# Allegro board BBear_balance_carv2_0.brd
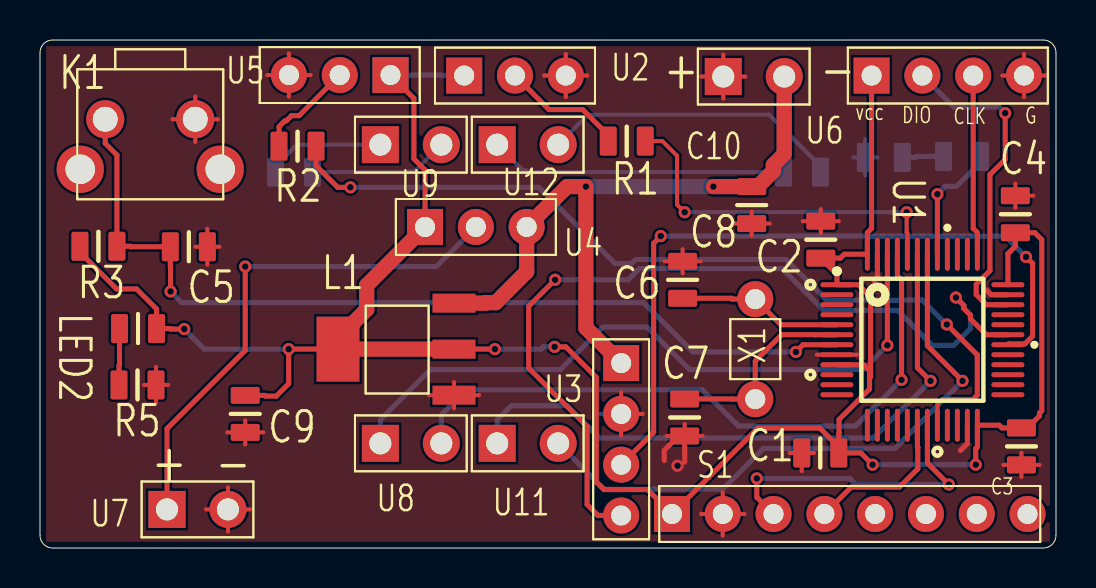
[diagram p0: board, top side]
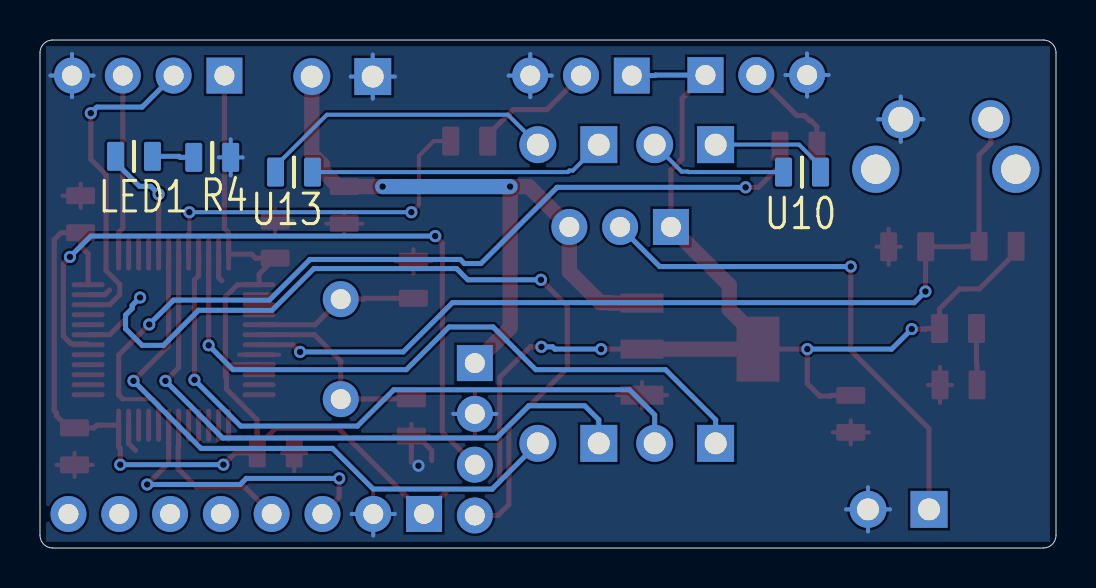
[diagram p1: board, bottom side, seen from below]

Outline 50.8 x 25.4 mm; copper layers: TOP, BOTTOM. Coordinates in mm from the lower left corner of the outline.
Outline path: 0,24.77 arc(0.19,25.21) 0.63,25.4 50.16,25.4 arc(50.61,25.21) 50.8,24.77 50.8,0.63 arc(50.61,0.19) 50.16,0 0.63,0 arc(0.19,0.19) 0,0.63 0,24.77

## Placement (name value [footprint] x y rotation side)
C1  0.1UF  [C-0805]  39.01 4.75 0 top
C2  0.1UF  [C-0805]  39.04 15.42 270 top
C3  0.1UF  [C-0805]  49.07 5.08 90 top
C4  0.1UF  [C-0805]  48.77 16.69 270 top
C5  1UF  [C-0805]  7.44 15.06 180 top
C6  22PF  [C-0805]  32.13 13.41 270 top
C7  22PF  [C-0805]  32.23 6.53 90 top
C8  0.1UF  [C-0805]  35.59 17.14 270 top
C9  10UF  [C-0805]  10.26 6.71 90 top
C10  POWER  [CON2_R2_54]  34.16 23.57 90 top
K1  KEY-4  [BUTTON_6X6X5]  5.51 21.44 180 top
L1  LM1117  [LM1117_3_3]  20.7 12.24 180 top
LED1  HEARTLED  [C-0805]  46.1 19.58 0 bottom
LED2  POWER  [C-0805]  4.9 10.97 0 top
R1  10K  [C-0805]  29.34 20.35 0 top
R2  10K  [C-0805]  12.88 20.09 0 top
R3  10K  [C-0805]  2.92 15.09 0 top
R4  1K  [C-0805]  42.19 19.53 180 bottom
R5  1K  [C-0805]  4.88 8.15 0 top
S1  MPU6050  [CON8]  31.6 1.7 90 top
U1  STM32F103C8T6  [NCU100_LQFP_48]  44.12 10.41 0 top
U2  BOOT0  [CON3]  21.21 23.62 90 top
U3  -  [CON4]  29.06 9.25 0 top
U4  switch  [CON3]  19.25 16.05 90 top
U5  BOOT1  [CON3]  17.53 23.65 270 top
U6  SWD  [CON4]  41.58 23.62 90 top
U7  CON2  [CON2_R2_54]  6.35 1.93 90 top
U8  CON2  [CON2_R2_54]  17.02 5.23 90 top
U9  MOTOR-A  [CON2_R2_54]  17.02 20.17 90 top
U10  MOTOR0805  [C-0805]  12.7 18.8 180 bottom
U11  CON2  [CON2_R2_54]  22.86 5.23 90 top
U12  MOTOR-B  [CON2_R2_54]  22.86 20.17 90 top
U13  MOTOR0805  [C-0805]  38.1 18.8 180 bottom
X1  -  [XTAL]  35.76 7.44 90 top

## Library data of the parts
C1-C9 = CAP: Tolerance: RichardLC; User Part Number: pn
C10 U7-U9 U11 U12 = CON2
K1 = KEY-4
L1 = LM1117
LED1 LED2 = LED: Tolerance: RichardLC; User Part Number: pn
R1-R5 = R: Tolerance: RichardLC; User Part Number: pn
S1 = CON8
U1 = STM32F103C8T6: User Part Number: pn; Tolerance: RichardLC
U2 U4 U5 = CON3
U3 U6 = CON4
U10 U13 = CON2: Tolerance: RichardLC; User Part Number: pn
X1 = XTAL

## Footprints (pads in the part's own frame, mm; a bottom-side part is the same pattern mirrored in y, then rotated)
BUTTON_6X6X5
  round 1.905 hole 1.245: 1(-2.25,0) 2(2.25,0)
  round 2.362 hole 1.473: 3(-3.5,2.5) 4(3.5,2.5)
C-0805
  custom 0.212x0.212 smd: 1(-0.925,0) 2(0.925,0)
CON2_R2_54
  rect 1.849x1.849 hole 1.1: 1(0,0)
  round 1.849 hole 1.1: 2(0,-3.048)
CON3
  rect 1.8x1.8 hole 1: 1(0,0)
  round 1.8 hole 1: 2(0,-2.54) 3(0,-5.08)
CON4
  rect 1.8x1.8 hole 1: 1(0,0)
  round 1.8 hole 1: 2(0,-2.54) 3(0,-5.08) 4(0,-7.62)
CON8
  rect 1.8x1.8 hole 1: 1(0,0)
  round 1.8 hole 1: 2(0,-2.54) 3(0,-5.08) 4(0,-7.62) 5(0,-10.16) 6(0,-12.7) 7(0,-15.24) 8(0,-17.78)
LM1117_3_3
  rect 2.15x0.95 smd: 1(0,0) 2(0,2.3) 3(0,4.6)
  rect 2.15x3.25 smd: 4(5.8,2.3)
NCU100_LQFP_48
  oval 1.651x0.249 smd: 1(-4.275,2.75) 2(-4.275,2.25) 3(-4.275,1.75) 4(-4.275,1.25) 5(-4.275,0.75) 6(-4.275,0.25) 7(-4.275,-0.25) 8(-4.275,-0.75) 9(-4.275,-1.25) 10(-4.275,-1.75) 11(-4.275,-2.25) 12(-4.275,-2.75) 25(4.275,-2.75) 26(4.275,-2.25) 27(4.275,-1.75) 28(4.275,-1.25) 29(4.275,-0.75) 30(4.275,-0.25) 31(4.275,0.25) 32(4.275,0.75) 33(4.275,1.25) 34(4.275,1.75) 35(4.275,2.25) 36(4.275,2.75)
  oval 0.249x1.651 smd: 13(-2.75,-4.275) 14(-2.25,-4.275) 15(-1.75,-4.275) 16(-1.25,-4.275) 17(-0.75,-4.275) 18(-0.25,-4.275) 19(0.25,-4.275) 20(0.75,-4.275) 21(1.25,-4.275) 22(1.75,-4.275) 23(2.25,-4.275) 24(2.75,-4.275) 37(2.75,4.275) 38(2.25,4.275) 39(1.75,4.275) 40(1.25,4.275) 41(0.75,4.275) 42(0.25,4.275) 43(-0.25,4.275) 44(-0.75,4.275) 45(-1.25,4.275) 46(-1.75,4.275) 47(-2.25,4.275) 48(-2.75,4.275)
XTAL
  round 1.8 hole 1: 1(0,0) 2(5,0)

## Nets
GND: C1.1 C2.1 C3.1 C4.1 C5.1 C6.1 C7.1 C8.2 C9.1 C10.1(-) K1.1 L1.3(GND) R4.2 R5.2 S1.2 U1.8(VSSA) U1.23(VSS_1) U1.35(VSS_2) U1.47(VSS_3) U2.3 U3.2 U5.3 U6.4 U7.2
VCC3.3: C1.2 C2.2 C3.2 C4.2 C9.2 L1.2(OUT2) L1.4(OUT1) LED2.2 R3.1 S1.1 U1.1(VBAT) U1.9(VDDA) U1.24(VDD_1) U1.36(VDD_2) U1.48(VDD_3) U2.1 U4.1 U5.1 U6.1
BAT_D: C8.1 C10.2(+) L1.1(VCC-IN) U3.1 U4.3
BOOT0: R1.2 U1.44(BOOT0)
BOOT1: R2.2 U1.20(PB2/BOOT1)
HEART_LED: LED1.2 U1.41(PB5)
LEFT_BACK: U1.43(PB7) U11.1
LEFT_FOR: U1.42(PB6) U11.2
MOTOR_BAT: U4.2 U7.1
OSCIN: C6.2 U1.5(OSCIN) X1.2
OSCOUT: C7.2 U1.6(OSCOUT) X1.1
PA9: U1.31(PA10) U3.4
PA10: U1.30(PA9) U3.3
RESET: C5.2 K1.2 R3.2 U1.7(NRST)
RIGHT_BACK: U1.46(PB9) U8.1
RIGHT_FOR: U1.45(PB8) U8.2
SCL: S1.3 U1.19(PB1)
SDA: S1.4 U1.18(PB0)
SWCLK: U1.37(SWCLK) U6.3
SWIO: U1.34(SWIO) U6.2
N03806: LED2.1 R5.1
N07785: LED1.1 R4.1
N23990: U9.1 U10.2
N23994: U9.2 U10.1
N23998: U12.1 U13.2
N24002: U12.2 U13.1
N073361: R1.1 U2.2
N073541: R2.1 U5.2

Pads without a net: K1 3 4; S1 5 6 7 8; U1 2 3 4 10 11 12 13 14 15 16 17 21 22 25 26 27 28 29 32 33 38 39 40

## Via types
v1: diameter 0.61, hole 0.33, TOP to BOTTOM, 28 vias

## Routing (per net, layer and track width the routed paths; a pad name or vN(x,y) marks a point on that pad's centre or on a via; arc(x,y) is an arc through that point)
GND: length 108.9
  TOP w0.203: U3.2 29.06,7.78 ; U3.2 30.14,6.71 ; U3.2 29.06,5.63 ; 38.84,9.66 U1.8 40.85,9.66 ; 5.8,7.25 R5.2 ; R5.2 5.8,9.06 ; R5.2 6.4,8.15 ; R5.2 5.2,8.15 ; K1.1 8.89,21.44 ; K1.1 6.63,21.44 ; K1.1 7.76,20.31 ; K1.1 7.76,22.57 ; C1.1 38.69,4.75 ; C1.1 37.49,4.75 ; C1.1 38.09,3.85 ; 33.06,23.57 C10.1 ; C10.1 34.16,24.67 ; C10.1 34.16,22.47 ; C10.1 35.27,23.57 ; C2.1 39.94,16.34 ; C2.1 38.14,16.34 ; C2.1 39.04,15.74 ; C2.1 39.04,16.95 ; C8.2 35.59,16.82 ; C8.2 34.68,16.22 ; C8.2 35.59,15.62 ; C8.2 36.49,16.22 ; C4.1 48.77,18.22 ; C4.1 49.67,17.61 ; C4.1 48.77,17.01 ; 26.29,22.54 26.29,23.62 ; 26.29,23.62 25.21,23.62 ; 26.29,23.62 26.29,24.7 ; 26.29,23.62 27.37,23.62 ; 19.45,7.64 L1.3 ; L1.3 20.7,6.99 ; L1.3 20.7,8.3 ; L1.3 21.95,7.64 ; 33.13,5.6 C7.1 32.23,6.21 ; 8.37,14.16 C5.1 ; C5.1 7.76,15.06 ; C5.1 8.97,15.06 ; C5.1 8.37,15.96 ; 48.12,23.62 U6.4 ; U6.4 50.28,23.62 ; U6.4 49.2,24.7 ; U6.4 49.2,22.54 ; 48.17,4.15 C3.1 ; C3.1 49.07,4.76 ; C3.1 49.07,3.55 ; C3.1 49.98,4.15 ; 33.06,1.7 S1.2 ; S1.2 34.14,2.78 ; S1.2 34.14,0.62 ; S1.2 35.22,1.7 ; 12.45,22.57 U5.3 ; U5.3 12.45,24.73 ; U5.3 13.52,23.65 ; U5.3 11.37,23.65 ; 32.13,13.73 C6.1 ; C6.1 33.03,14.34 ; C6.1 31.23,14.34 ; C6.1 32.13,14.94 ; 8.3,1.93 U7.2 ; U7.2 10.5,1.93 ; U7.2 9.4,0.83 ; U7.2 9.4,3.03 ; 31.33,5.6 31.93,5.6 ; 10.26,5.18 C9.1 ; C9.1 11.16,5.78 ; C9.1 9.36,5.78 ; C9.1 10.26,6.38
  TOP w0.254: U1.47 41.87,13.52 41.71,13.36 ; U1.23 46.37,5.22 46.02,4.88 ; U1.35 47.56,12.66 47.32,12.9 ; 31.22,4.37 31.22,4.89 31.93,5.6 C7.1 32.23,4.29
  BOTTOM w0.203: U7.2 10.5,1.93 ; U7.2 9.4,3.03 ; U7.2 8.3,1.93 ; U7.2 9.4,0.83 ; 33.06,1.7 S1.2 ; S1.2 35.22,1.7 ; S1.2 34.14,0.62 ; U6.4 50.28,23.62 ; U6.4 49.2,22.54 ; U6.4 48.12,23.62 ; U6.4 49.2,24.7 ; 7.76,20.31 K1.1 ; K1.1 7.76,22.57 ; K1.1 8.89,21.44 ; K1.1 6.63,21.44 ; 26.29,23.62 26.29,24.7 ; 26.29,23.62 26.29,22.54 ; 26.29,23.62 25.21,23.62 ; 26.29,23.62 27.37,23.62 ; 30.14,6.71 U3.2 27.98,6.71 ; 12.45,22.57 U5.3 ; U5.3 12.45,24.73 ; U5.3 11.37,23.65 ; U5.3 13.52,23.65 ; 33.06,23.57 C10.1 ; C10.1 35.27,23.57 ; C10.1 34.16,22.47 ; C10.1 34.16,24.67 ; R4.2 41.26,20.43 ; R4.2 41.87,19.53 ; R4.2 40.66,19.53 ; R4.2 41.26,18.63
  vias: v1(31.88,4.11)
VCC3.3: length 124.8
  TOP w0.254: 39.94,5.05 39.94,5.73 39.95,5.74 39.95,6.43 41.48,7.95 41.48,8.51 ; 39.94,5.05 38.99,5.99 35.89,5.99 S1.1 30.38,2.92 28.19,2.92 27.81,3.3 27.81,8.53 26.29,10.06 v1(25.73,10.06) ; 39.94,5.05 C1.2 41.05,4.75 v1(41.63,4.17) ; v1(7.21,10.95) 6.53,10.95 6.51,10.97 LED2.2 5.83,11.95 4.82,12.95 3.83,12.95 2,14.79 R3.1 ; C9.2 11.24,7.63 11.28,7.59 11.81,7.59 12.43,8.22 v1(12.43,9.94) L1.4 ; 41.48,8.51 41.48,8.86 41.18,9.16 U1.9 ; 41.48,8.51 41.53,8.56 41.53,12.56 40.92,13.16 U1.1 39.84,13.69 C2.2 40.02,14.49 40.21,14.69 U1.48 41.37,15.77 41.58,15.98 U6.1 ; U4.1 19.25,18.9 18.69,19.46 18.69,22.48 U5.1 ; v1(46.79,4.17) 46.79,4.98 46.87,5.06 U1.24 47.96,6.14 48.09,6.01 C3.2 49.37,6.01 49.98,6.61 49.98,6.75 50.09,6.86 50.09,15.42 49.75,15.76 C4.2 48.77,15.08 48.39,14.71 U1.36 ; L1.2 v1(22.74,9.94)
  TOP w0.762: L1.2 L1.4 14.9,10.49 16.34,11.93 16.34,13.14 U4.1
  BOTTOM w0.254: v1(25.73,10.06) 25.17,10.06 25.06,9.94 v1(22.74,9.94) ; v1(12.43,9.94) 8.22,9.94 v1(7.21,10.95) ; U5.1 20.03,23.65 20.05,23.62 U2.1 ; v1(41.63,4.17) v1(46.79,4.17)
BAT_D: length 34.5
  TOP w0.762: C10.2 37.21,19.7 36.67,19.15 36.67,18.85 35.89,18.07 C8.1 v1(33.67,18.07) ; L1.1 22.28,12.24 22.31,12.27 22.78,12.27 24.33,13.82 U4.3 26.35,18.07 v1(27.29,18.07) 27.29,11.01 U3.1
  BOTTOM w0.762: v1(33.67,18.07) v1(27.29,18.07)
BOOT0: length 18.1
  TOP w0.203: v1(32.23,16.79) 31.85,17.17 31.85,19.61 31.11,20.35 R1.2 ; v1(43.33,16.79) 43.33,15.78 43.37,15.74 U1.44
  BOTTOM w0.203: v1(32.23,16.79) v1(43.33,16.79)
BOOT1: length 43.4
  TOP w0.203: 46.66,7.44 45.12,7.44 44.87,7.19 U1.20
  TOP w0.254: v1(15.52,18.03) 14.88,18.03 13.8,19.11 R2.2 ; 46.66,7.44 46.86,7.65 46.86,9.65 v1(45.34,11.18)
  BOTTOM w0.254: v1(45.34,11.18) 44.12,12.4 39.33,12.4 37.3,14.43 29.78,14.43 29.58,14.22 28.75,14.22 24.94,18.03 v1(15.52,18.03)
HEART_LED: length 6.1
  TOP w0.254: U1.41 v1(44.87,17.69)
  BOTTOM w0.254: LED1.2 47.03,19.28 45.83,18.09 45.27,18.09 v1(44.87,17.69)
LEFT_BACK: length 31.6
  TOP w0.254: U1.43 43.87,9.01 v1(44.53,8.36)
  BOTTOM w0.254: U11.1 22.86,6.41 23.56,7.11 26.37,7.11 27.98,5.5 41.67,5.5 v1(44.53,8.36)
LEFT_FOR: length 30.5
  TOP w0.254: U1.42 44.37,10.11 v1(46.13,8.36)
  BOTTOM w0.254: U11.2 28.19,2.95 34.14,2.95 36.17,4.98 42.75,4.98 v1(46.13,8.36)
MOTOR_BAT: length 26.1
  TOP w0.254: v1(10.26,14.07) 10.26,9.88 6.35,5.97 U7.1
  BOTTOM w0.254: U4.2 19.81,14.07 v1(10.26,14.07)
OSCIN: length 8.3
  TOP w0.254: U1.5 37.04,11.16 X1.2 34.61,12.44 34.57,12.49 C6.2
OSCOUT: length 10.1
  TOP w0.254: C7.2 34.6,7.45 34.61,7.44 X1.1 35.76,9.35 37.08,10.67 38.76,10.67 38.77,10.66 U1.6
PA9: length 43.3
  TOP w0.254: U1.31 47.32,10.66 46.52,11.46 46.52,11.64 46.19,11.97 46.19,12.13 v1(45.8,12.52) ; U3.4 27.9,1.63 27.36,2.17 27.36,6.07 24.43,8.99 24.43,12.09 v1(25.76,13.41)
  BOTTOM w0.254: v1(25.76,13.41) 29.41,13.41 29.97,13.97 37.11,13.97 39.19,11.89 42.88,11.89 44.63,10.13 45.69,10.13 46.52,10.96 46.52,11.64 46.19,11.97 46.19,12.13 v1(45.8,12.52)
PA10: length 36.5
  TOP w0.254: v1(49.3,14.55) 49.63,14.22 49.63,10.59 49.25,10.21 48.44,10.21 U1.30 ; U3.3 30.68,5.79 30.68,15.24 v1(31.04,15.6)
  BOTTOM w0.254: v1(49.3,14.55) 48.26,15.6 v1(31.04,15.6)
RESET: length 46.2
  TOP w0.254: K1.2 3.26,20.23 3.85,19.65 R3.2 4.52,15.09 4.55,15.06 C5.2 6.52,14.08 6.53,14.07 v1(6.53,12.83) ; U1.7 38.15,10.16 v1(37.8,9.8)
  BOTTOM w0.254: v1(37.8,9.8) 32.64,9.8 30.18,12.27 7.09,12.27 v1(6.53,12.83)
RIGHT_BACK: length 34.4
  TOP w0.254: U1.46 42.37,13.61 42.37,13.61 v1(42.37,10.13)
  BOTTOM w0.254: U8.1 17.02,6.41 19.52,8.92 26.01,8.92 28.14,11.05 30.35,11.05 32.49,8.92 41.15,8.92 v1(42.37,10.13)
RIGHT_FOR: length 33
  TOP w0.254: v1(43.08,8.41) 43.08,13.4 42.87,13.61 U1.45
  BOTTOM w0.254: v1(43.08,8.41) 40.77,6.1 34.92,6.1 33.11,7.91 21.32,7.91 20.07,6.65 U8.2
SCL: length 15.3
  TOP w0.254: U1.19 44.37,4.7 44.37,4.7 44.37,4.24 v1(45.44,3.17) ; S1.3 35.84,2.54 v1(35.84,3.48)
  BOTTOM w0.254: v1(35.84,3.48) 40.49,3.48 40.79,3.17 v1(45.44,3.17)
SDA: length 7.8
  TOP w0.254: U1.18 43.87,5.06 43.89,5.04 43.89,3.96 42.98,3.05 40.56,3.05 S1.4
SWCLK: length 9
  TOP w0.254: U6.3 46.66,15.98 46.87,15.77 U1.37
SWIO: length 16.4
  TOP w0.254: v1(48.26,21.74) 48.26,19.43 47.5,18.67 47.5,13.87 46.81,13.18 46.81,12.67 47.32,12.16 U1.34
  BOTTOM w0.254: v1(48.26,21.74) 47.96,22.05 45.69,22.05 U6.2
N03806: length 2.8
  TOP w0.254: R5.1 3.95,9.13 3.98,9.16 LED2.1
N07785: length 2.1
  BOTTOM w0.254: R4.1 43.79,19.53 43.84,19.58 LED1.1
N23990: length 6
  BOTTOM w0.203: U9.1 12.85,20.17 11.77,19.1 U10.2
N23994: length 7
  BOTTOM w0.203: U9.2 18.72,18.82 18.41,18.82 18.39,18.8 U10.1
N23998: length 14.9
  BOTTOM w0.203: U13.2 24.41,18.8 24.33,18.87 24.16,18.87 U12.1
N24002: length 15.1
  BOTTOM w0.203: U13.1 39.03,19.1 36.45,21.67 27.41,21.67 U12.2
N073361: length 6.2
  TOP w0.254: 23.75,23.62 25.45,21.92 27.14,21.92 28.41,20.65 R1.1
N073541: length 5.1
  TOP w0.254: U5.2 12.95,21.62 12.57,21.62 12.32,21.36 12.24,21.36 11.95,21.07 R2.1

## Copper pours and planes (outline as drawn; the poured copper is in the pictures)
GND on TOP: 0.31,0.31 0.31,25.09 50.49,25.09 50.49,0.33 50.47,0.31 ; 5 cut-outs
GND on BOTTOM: 0.31,0.31 0.31,25.09 50.49,25.09 50.49,0.31

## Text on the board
Ref Des/Silkscreen Top: vcc | DIO | CLK | G | + | -
COMPVAL_TYPE_BOTTOM: FIGURE | SIZE | 13.0 | 39.37 | 43.3 | 49.0 | 58.0 | DRILL CHART: TOP to BOTTOM | ALL UNITS ARE IN MILS | PLATED | QTY | 28 | 27 | 12 | 2
